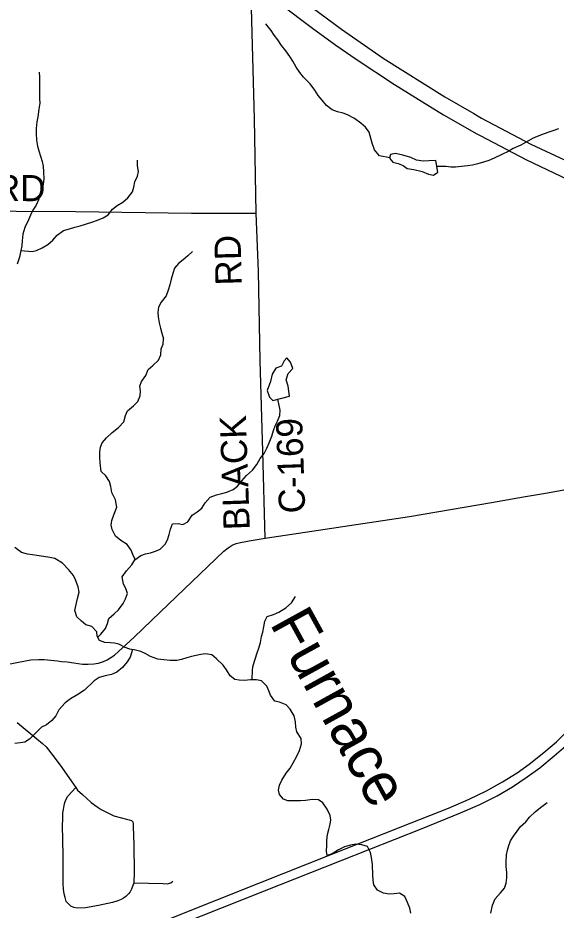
# Model space of a CAD drawing. Extents: x 0 to 34, y 0 to 22.
# Drawn here: x 6.774 to 7.942, y 17.94 to 19.877 of the extents above; entities that cross this region are included whole.
import ezdxf

# ---------------------------------------------------------------- set-up
doc = ezdxf.new("R2010")
doc.units = 0
for name, color, linetype in [('GM_X_County_Road', 7, 'Continuous'), ('GM_X_County_Road_Text', 7, 'Continuous'), ('GM_X_Interstate_Route', 7, 'Continuous'), ('GM_X_Minor_Lake', 7, 'Continuous'), ('GM_X_Minor_River', 7, 'Continuous'), ('GM_X_Minor_River_Text', 7, 'Continuous'), ('GM_X_State_Route', 7, 'Continuous'), ('GM_X_Township_Road', 7, 'Continuous')]:
    doc.layers.add(name, color=color, linetype=linetype)

msp = doc.modelspace()

# ---------------------------------------------------------------- linework, layer by layer
at = {"layer": 'GM_X_County_Road'}
for points in [[(7.3109, 18.7479), (7.3061, 18.9361), (7.3003, 19.1331), (7.296, 19.3266), (7.2915, 19.4531), (7.2874, 19.6581), (7.2805, 19.9253)], [(6.6415, 19.4581), (6.8998, 19.4568), (7.1507, 19.4535), (7.2915, 19.4531)]]:
    msp.add_lwpolyline(points, dxfattribs=at)
at = {"layer": 'GM_X_Interstate_Route'}
for points in [[(6.7966, 20.4252), (6.9486, 20.2925), (7.156, 20.1111), (7.2785, 20.0062), (7.3237, 19.9679), (7.3987, 19.9098), (7.4761, 19.8527), (7.5666, 19.7895), (7.7006, 19.7055), (7.763, 19.6693)], [(6.7749, 20.3983), (6.8079, 20.3699), (6.8685, 20.317), (6.9085, 20.2814), (6.9964, 20.2046), (7.0553, 20.1519), (7.149, 20.0706), (7.2156, 20.0127), (7.2801, 19.959), (7.343, 19.9077), (7.4133, 19.8545), (7.4638, 19.8177), (7.5083, 19.7871), (7.5915, 19.7321), (7.6978, 19.6669), (7.77, 19.6256)], [(7.763, 19.6693), (7.7803, 19.6592), (7.8872, 19.6029), (7.9722, 19.5629), (8.0288, 19.5381), (8.0798, 19.5173), (8.133, 19.4976), (8.2063, 19.4731), (8.2759, 19.4521), (8.3193, 19.44), (8.3644, 19.4294), (8.4096, 19.4189), (8.4631, 19.4094), (8.4883, 19.4042), (8.5449, 19.3944), (8.5849, 19.3884), (8.632, 19.3823), (8.676, 19.3776), (8.7165, 19.3744), (8.7499, 19.3726), (8.7881, 19.3707), (8.827, 19.3697), (8.8657, 19.3686), (8.9, 19.3694)], [(7.77, 19.6256), (7.777, 19.6216), (7.8775, 19.5687), (7.967, 19.5263), (8.0323, 19.4989), (8.096, 19.4742), (8.2071, 19.4363), (8.2852, 19.4131), (8.3666, 19.3924), (8.3941, 19.3871)], [(7.1051, 17.9225), (7.2044, 17.9618), (7.2972, 17.9988), (7.4555, 18.0618), (7.6271, 18.1297), (7.7081, 18.1617), (7.7533, 18.1809), (7.7907, 18.1993), (7.8258, 18.2185), (7.8572, 18.2381), (7.8837, 18.2574), (7.9154, 18.2825), (7.9424, 18.306), (7.9856, 18.3489), (8.0262, 18.3952), (8.0574, 18.4379), (8.0852, 18.484), (8.1047, 18.5208), (8.1243, 18.5652), (8.1648, 18.6761), (8.2052, 18.7856), (8.2159, 18.8158)], [(7.1275, 17.9096), (7.3095, 17.9823), (7.4758, 18.048), (7.6514, 18.1175), (7.7344, 18.1512), (7.7767, 18.1695), (7.814, 18.1886), (7.847, 18.2083), (7.879, 18.2298), (7.9063, 18.2489), (7.9379, 18.2751), (7.9628, 18.2973)]]:
    msp.add_lwpolyline(points, dxfattribs=at)
at = {"layer": 'GM_X_Minor_Lake'}
for points in [[(7.6807, 19.5672), (7.6655, 19.5671), (7.6538, 19.5658), (7.639, 19.568), (7.6264, 19.5743), (7.6093, 19.5791), (7.5938, 19.5824), (7.5828, 19.5804), (7.5806, 19.5724), (7.5879, 19.5637), (7.5996, 19.5611), (7.6103, 19.5563), (7.6187, 19.5503), (7.6335, 19.5478), (7.651, 19.5438), (7.6654, 19.5378), (7.6761, 19.5353), (7.6855, 19.5422)], [(7.6855, 19.5422), (7.6807, 19.5672)], [(7.3637, 19.0557), (7.3609, 19.078), (7.3566, 19.0917), (7.3607, 19.1054), (7.3708, 19.1157), (7.3658, 19.1297), (7.3581, 19.1395), (7.3517, 19.1326), (7.3461, 19.1208), (7.334, 19.1169), (7.3262, 19.1035), (7.3222, 19.0875), (7.3155, 19.0685), (7.3205, 19.0537), (7.3271, 19.0466)], [(7.3271, 19.0466), (7.3637, 19.0557)]]:
    msp.add_lwpolyline(points, dxfattribs=at)
at = {"layer": 'GM_X_Minor_River'}
for points in [[(7.5809, 19.5735), (7.5589, 19.5775), (7.5482, 19.5907), (7.5432, 19.6051), (7.5361, 19.6293), (7.5285, 19.6395), (7.5185, 19.6485), (7.5048, 19.659), (7.4896, 19.6665), (7.4797, 19.6702), (7.4679, 19.6731), (7.4561, 19.6776), (7.4439, 19.6869), (7.4343, 19.6983), (7.4259, 19.7084), (7.4182, 19.7205), (7.4082, 19.7341), (7.3941, 19.7484), (7.3857, 19.7582), (7.378, 19.7703), (7.371, 19.7831), (7.3645, 19.7933), (7.3553, 19.8054), (7.3465, 19.8171), (7.3384, 19.8296), (7.3304, 19.8397), (7.3235, 19.8496), (7.3124, 19.8639)], [(6.8205, 19.7593), (6.8217, 19.7486), (6.8211, 19.7361), (6.8213, 19.7133), (6.8217, 19.7015), (6.8218, 19.6916), (6.82, 19.6791), (6.8175, 19.662), (6.8157, 19.6513), (6.814, 19.6369), (6.8141, 19.6262), (6.8149, 19.6114), (6.8173, 19.5985), (6.8197, 19.5887), (6.8236, 19.5769), (6.8271, 19.5655), (6.8291, 19.5553), (6.8303, 19.5428), (6.8305, 19.5272), (6.8294, 19.5162), (6.8269, 19.5048), (6.8235, 19.4937), (6.8195, 19.4819), (6.8139, 19.4708), (6.8072, 19.4594), (6.8016, 19.449), (6.7975, 19.4384), (6.7893, 19.4219), (6.7852, 19.4078), (6.7839, 19.393), (6.7828, 19.382), (6.781, 19.3721), (6.7777, 19.3576), (6.7729, 19.3424)], [(7.947, 19.6359), (7.9371, 19.6328), (7.9258, 19.6292), (7.9077, 19.6226), (7.8922, 19.616), (7.8805, 19.6098), (7.865, 19.6009), (7.8488, 19.5932), (7.839, 19.5877), (7.8239, 19.5804), (7.8076, 19.5726), (7.7959, 19.5676), (7.7842, 19.564), (7.7721, 19.5605), (7.7608, 19.5574), (7.7494, 19.5557), (7.7369, 19.5541), (7.7237, 19.5528), (7.7138, 19.5531), (7.7036, 19.5545), (7.6831, 19.5547)], [(6.781, 19.3721), (6.8053, 19.37), (6.8151, 19.372), (6.8272, 19.3779), (6.8396, 19.3852), (6.8506, 19.3944), (6.8599, 19.4055), (6.8735, 19.4152), (6.8867, 19.4195), (6.8977, 19.4226), (6.9098, 19.4258), (6.9347, 19.4336), (6.9472, 19.4379), (6.9597, 19.443), (6.9706, 19.4499), (6.9796, 19.4621), (6.9898, 19.4698), (7.0018, 19.4768), (7.0128, 19.4868), (7.0229, 19.4998), (7.0258, 19.5093), (7.0284, 19.5215), (7.034, 19.5337), (7.0361, 19.5436), (7.0341, 19.5557), (7.034, 19.5683)], [(7.1529, 19.3699), (7.1431, 19.3604), (7.1329, 19.3519), (7.1232, 19.3442), (7.1141, 19.3335), (7.1105, 19.322), (7.1068, 19.3102), (7.1042, 19.2977), (7.1005, 19.2859), (7.0961, 19.2737), (7.0856, 19.2603), (7.0796, 19.2488), (7.0782, 19.2374), (7.0787, 19.2279), (7.0807, 19.215), (7.0838, 19.2036), (7.0866, 19.193), (7.0905, 19.1805)], [(7.0292, 18.7017), (7.0236, 18.7121), (7.0201, 18.722), (7.0113, 18.734), (6.998, 18.7423), (6.9865, 18.7524), (6.9788, 18.7664), (6.9768, 18.7763), (6.9783, 18.7861), (6.9827, 18.7983), (6.989, 18.8147), (6.9862, 18.831), (6.9785, 18.8469), (6.9758, 18.8598), (6.9734, 18.8704), (6.9649, 18.8829), (6.9554, 18.8926), (6.9533, 18.9116), (6.9525, 18.9245), (6.952, 18.9348), (6.9534, 18.945), (6.9571, 18.9546), (6.9669, 18.9653), (6.9789, 18.9768), (6.9929, 18.9879), (7.0041, 19.0002), (7.0082, 19.0143), (7.0119, 19.0238), (7.025, 19.0353), (7.0348, 19.0446), (7.0396, 19.0568), (7.0403, 19.0678), (7.0391, 19.0773), (7.0424, 19.0875), (7.0518, 19.1005), (7.057, 19.1139), (7.0675, 19.1223), (7.0795, 19.1339), (7.0847, 19.1457), (7.0854, 19.159), (7.0899, 19.1685), (7.0905, 19.1805)], [(6.9477, 18.533), (6.9546, 18.5391), (6.9644, 18.5517), (6.9692, 18.5624), (6.9721, 18.573), (6.983, 18.5838), (6.9928, 18.5918), (7.0026, 18.6056), (7.0078, 18.6163), (7.0119, 18.6277), (7.0087, 18.6383), (7.0033, 18.6481), (7.0009, 18.6641), (7.0099, 18.6767), (7.0219, 18.6901), (7.0279, 18.7008), (7.0411, 18.7104), (7.0513, 18.7139), (7.0619, 18.7159), (7.0732, 18.7198), (7.0834, 18.7237), (7.0939, 18.7348), (7.0988, 18.7444), (7.1025, 18.7554), (7.1054, 18.7672), (7.1095, 18.779), (7.1224, 18.7799), (7.1319, 18.7773), (7.1428, 18.7835), (7.1522, 18.798), (7.1631, 18.805), (7.1736, 18.8131), (7.1807, 18.8241), (7.1916, 18.8364), (7.2049, 18.8418), (7.2166, 18.8446), (7.2279, 18.8474), (7.2411, 18.8532), (7.2509, 18.8609), (7.2603, 18.872), (7.2705, 18.8839), (7.2832, 18.8954), (7.2926, 18.9076), (7.2997, 18.9206), (7.3083, 18.9313), (7.3143, 18.9431), (7.3195, 18.955), (7.3254, 18.9691), (7.3287, 18.9816), (7.3325, 18.9915), (7.3377, 19.0015), (7.3429, 19.0137), (7.3432, 19.0255), (7.3384, 19.0494)], [(7.1412, 18.488), (7.1291, 18.4845), (7.1189, 18.4825), (7.1048, 18.482), (7.0908, 18.4834), (7.0783, 18.4852), (7.0623, 18.4907), (7.0509, 18.4974), (7.0414, 18.5019), (7.0269, 18.5056), (7.0171, 18.507), (7.0072, 18.5103), (6.9938, 18.5174), (6.9843, 18.5196), (6.9749, 18.5206), (6.9631, 18.5213), (6.9513, 18.5253), (6.9467, 18.5352), (6.9455, 18.5447), (6.9348, 18.5563), (6.9222, 18.5596), (6.9123, 18.5675), (6.9024, 18.5773), (6.8977, 18.5909), (6.9006, 18.6035), (6.9039, 18.6164), (6.9076, 18.6305), (6.9052, 18.6423), (6.8994, 18.657), (6.8951, 18.6669), (6.884, 18.68), (6.871, 18.6932), (6.8543, 18.7033), (6.8436, 18.7059), (6.83, 18.708), (6.8156, 18.7102), (6.8061, 18.7112), (6.7954, 18.713), (6.7825, 18.7167), (6.7676, 18.7276)], [(7.2826, 18.44), (7.2832, 18.4617), (7.285, 18.4712), (7.2894, 18.4849), (7.2931, 18.4986), (7.2968, 18.5089), (7.3005, 18.5211), (7.303, 18.534), (7.3056, 18.5439), (7.3078, 18.5553), (7.3103, 18.5675), (7.3148, 18.5778), (7.3288, 18.5821), (7.3405, 18.5871), (7.3555, 18.5968), (7.368, 18.6075), (7.3769, 18.6209)], [(7.0232, 18.5061), (7.018, 18.4891), (7.0112, 18.4796), (7.0011, 18.467), (6.9891, 18.457), (6.9773, 18.4519), (6.9641, 18.4491), (6.9509, 18.4456), (6.9399, 18.4379), (6.9189, 18.4179), (6.9042, 18.4087), (6.8887, 18.3987), (6.8774, 18.3902), (6.8635, 18.3749), (6.8568, 18.3623), (6.8478, 18.3516), (6.8369, 18.3427), (6.8259, 18.3373), (6.8135, 18.325), (6.8, 18.3116), (6.7895, 18.3051), (6.7792, 18.3034), (6.7679, 18.3022)], [(7.6269, 17.9336), (7.6242, 17.9446), (7.6195, 17.9571), (7.6134, 17.9699), (7.6023, 17.977), (7.5909, 17.9754), (7.58, 17.9753), (7.5678, 17.9775), (7.5545, 17.9834), (7.5468, 17.9955), (7.5448, 18.0053), (7.544, 18.0164), (7.5438, 18.0395), (7.5414, 18.0543), (7.5394, 18.0657), (7.5324, 18.0781), (7.5203, 18.0822), (7.5074, 18.0832), (7.4957, 18.0816), (7.4832, 18.0777), (7.4696, 18.0715), (7.456, 18.0622), (7.4451, 18.0587), (7.4438, 18.0682), (7.4445, 18.0807), (7.4444, 18.0917), (7.4458, 18.1043), (7.4491, 18.1153), (7.4517, 18.1268), (7.4531, 18.1363), (7.4519, 18.1461), (7.445, 18.1594), (7.4361, 18.1733), (7.4262, 18.1801), (7.4137, 18.1807), (7.3982, 18.1783), (7.3876, 18.1778), (7.3739, 18.1777), (7.3603, 18.1779), (7.3508, 18.1812), (7.3416, 18.191), (7.34, 18.2005), (7.3422, 18.2119), (7.347, 18.2222), (7.3563, 18.2375), (7.365, 18.2482), (7.3717, 18.2604), (7.3795, 18.2742), (7.3851, 18.2868), (7.3899, 18.3016), (7.3891, 18.3126), (7.3798, 18.3274), (7.3771, 18.3372), (7.3766, 18.349), (7.3739, 18.3619), (7.365, 18.3762), (7.3562, 18.386), (7.3421, 18.392), (7.3315, 18.3941), (7.3227, 18.4066), (7.3188, 18.4164), (7.3145, 18.4263), (7.3027, 18.4383), (7.2921, 18.4401), (7.2792, 18.44), (7.2663, 18.4391), (7.2545, 18.4397), (7.2451, 18.4412), (7.2348, 18.4487), (7.2267, 18.4619), (7.2198, 18.4721), (7.2052, 18.486), (7.1949, 18.4946), (7.1817, 18.4968), (7.1714, 18.4952), (7.1608, 18.4932), (7.151, 18.4908), (7.1412, 18.488)], [(7.8002, 17.9341), (7.8038, 17.9508), (7.8098, 17.9646), (7.8214, 17.9776), (7.83, 17.9883), (7.8333, 17.9986), (7.8351, 18.0108), (7.8347, 18.0218), (7.8334, 18.0354), (7.8333, 18.0449), (7.8343, 18.0605), (7.8361, 18.0708), (7.8391, 18.0803), (7.8432, 18.0906), (7.8495, 18.1009), (7.8574, 18.112), (7.8649, 18.1216), (7.8758, 18.1323), (7.8844, 18.1419), (7.8965, 18.1534), (7.9081, 18.163), (7.9221, 18.1738)]]:
    msp.add_lwpolyline(points, dxfattribs=at)
at = {"layer": 'GM_X_State_Route'}
msp.add_lwpolyline([(6.7427, 18.4722), (6.7759, 18.4789), (6.8025, 18.4833), (6.8202, 18.4846), (6.8318, 18.4843), (6.8458, 18.4832), (6.8603, 18.4814), (6.8693, 18.4802), (6.8811, 18.4793), (6.8958, 18.477), (6.9145, 18.4744), (6.9269, 18.474), (6.9389, 18.4749), (6.949, 18.4765), (6.9601, 18.4802), (6.9679, 18.4837), (6.9843, 18.4938), (7.0269, 18.5325), (7.0831, 18.5869), (7.2213, 18.7196), (7.2303, 18.7269), (7.2391, 18.7322), (7.248, 18.7361), (7.257, 18.7384), (7.2692, 18.7408), (7.2761, 18.742), (7.3109, 18.7479), (7.6235, 18.795), (7.8018, 18.8251), (7.8714, 18.8373), (7.9191, 18.8456), (7.9785, 18.8559)], dxfattribs=at)
at = {"layer": 'GM_X_Township_Road'}
for points in [[(6.773, 18.3477), (6.8154, 18.3125), (6.8281, 18.3017), (6.8355, 18.295), (6.841, 18.2883), (6.8484, 18.2786), (6.8661, 18.2549), (6.9, 18.2065), (6.9041, 18.201), (6.9145, 18.1911), (6.9237, 18.1823), (6.9338, 18.1743), (6.9463, 18.1648), (6.9552, 18.1591), (6.9709, 18.1505), (6.9829, 18.1452), (6.999, 18.1406), (7.0101, 18.1379), (7.0161, 18.1365), (7.0209, 18.1346), (7.0237, 18.1323)], [(6.949, 17.9506), (6.9214, 17.9451), (6.9036, 17.9443), (6.896, 17.9462), (6.889, 17.9492), (6.8841, 17.954), (6.8795, 17.9593), (6.8767, 17.9679), (6.8748, 17.9757), (6.8737, 17.9858), (6.873, 17.9973), (6.873, 18.0595), (6.8714, 18.1245), (6.8719, 18.1379), (6.8721, 18.1517), (6.8735, 18.1591), (6.8748, 18.1674), (6.8765, 18.1738), (6.8778, 18.1777), (6.8801, 18.1826), (6.8831, 18.1874), (6.9, 18.2065)], [(7.0237, 18.1323), (7.0246, 18.128), (7.0248, 18.1229), (7.0255, 18.1019), (7.026, 18.0823), (7.0267, 18.0222), (7.0262, 17.9996), (7.0211, 17.9861), (7.0177, 17.9798), (7.0142, 17.9757), (7.0085, 17.9702), (7.0039, 17.9662), (6.9986, 17.9632), (6.9914, 17.9605), (6.9799, 17.957), (6.949, 17.9506)], [(7.0262, 17.9996), (7.0898, 17.9985), (7.0985, 17.9973), (7.1061, 17.9999), (7.1107, 18.0031)]]:
    msp.add_lwpolyline(points, dxfattribs=at)

# ---------------------------------------------------------------- texts
at = {"layer": 'GM_X_County_Road_Text'}
for s, rotation, p in [('RD', 359.5064, (6.7243, 19.4798)), ('RD', 91.4806, (7.2601, 19.2969)), ('BLACK', 92.0089, (7.2776, 18.766)), ('C-169', 91.928, (7.3978, 18.8025))]:
    msp.add_text(s, height=0.05682, rotation=rotation, dxfattribs=at).set_placement(p)
at = {"layer": 'GM_X_Minor_River_Text'}
msp.add_text('Furnace', height=0.09475, rotation=298.8461, dxfattribs=at).set_placement((7.3196, 18.5627))

doc.saveas('drawing.dxf')
